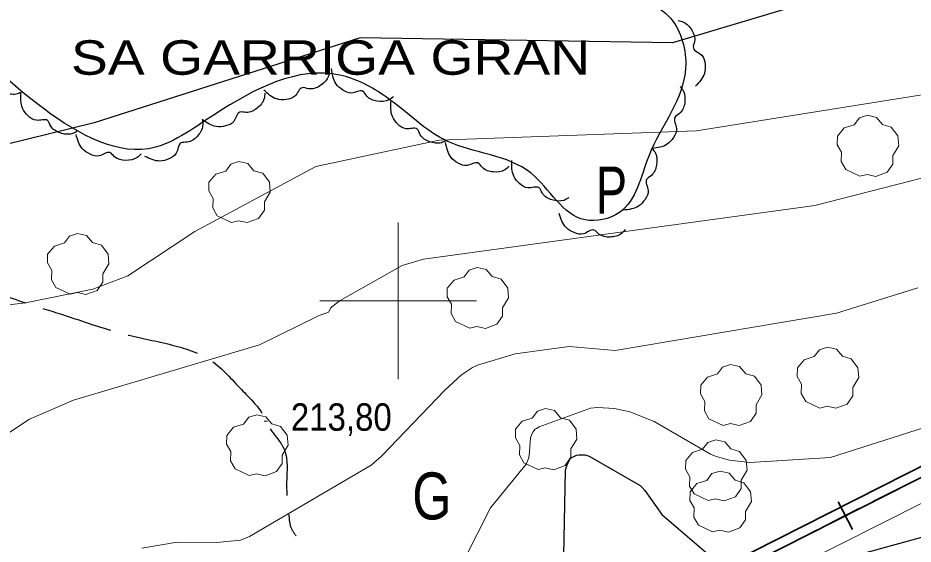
# Model space of a CAD drawing. Extents: x 480269 to 484877, y 4383588 to 4386804.
# Drawn here: x 483378.6 to 483664.3, y 4384922.4 to 4385090.3 of the extents above; entities that cross this region are included whole.
import ezdxf
from ezdxf.enums import TextEntityAlignment as Align

# ---------------------------------------------------------------- set-up
doc = ezdxf.new("R2010")
doc.units = 0
doc.header["$LTSCALE"] = 3.8
doc.linetypes.add('LONG_DASHED', pattern=[7.5, 6, -1.5])
for name, color, linetype, lineweight in [('1', 7, 'Continuous', 13), ('27', 7, 'Continuous', 25), ('29', 7, 'Continuous', 13), ('34', 7, 'Continuous', 35), ('38', 7, 'Continuous', 25), ('51', 7, 'Continuous', 13), ('7', 7, 'Continuous', 13), ('8', 7, 'Continuous', 25), ('9', 7, 'Continuous', 13)]:
    doc.layers.add(name, color=color, linetype=linetype, lineweight=lineweight)
doc.layers.add('31', color=7, linetype='Continuous')
doc.layers.add('5', color=7, linetype='Continuous')

msp = doc.modelspace()

# ---------------------------------------------------------------- linework, layer by layer
at = {"layer": '1'}
for p, q in [((483500, 4385025), (483500, 4384975)), ((483475, 4385000), (483525, 4385000))]:
    msp.add_line(p, q, dxfattribs=at)
at = {"layer": '27'}
for points in [[(483727.16, 4385128.45), (483702.11, 4385129.24), (483649.65, 4385135.5), (483626.16, 4385132.37), (483588.58, 4385137.07), (483567.44, 4385128.45), (483561.17, 4385115.92), (483569.79, 4385101.04), (483587.01, 4385090.07), (483591.71, 4385074.4), (483579.96, 4385046.2), (483570.57, 4385028.19), (483559.61, 4385025.84), (483542.38, 4385040.72), (483515.76, 4385050.9), (483496.19, 4385065), (483481.31, 4385072.05), (483441.38, 4385059.52), (483420.24, 4385048.55), (483385, 4385062.65), (483357.6, 4385086.15), (483334.89, 4385110.44), (483327.07, 4385140.2), (483309.84, 4385151.17), (483298.1, 4385151.17), (483281.65, 4385134.72), (483253.47, 4385133.15), (483239.37, 4385137.85), (483220.58, 4385130.8), (483190.05, 4385142.55), (483153.25, 4385156.65), (483117.23, 4385145.69), (483096.09, 4385136.29), (483050.68, 4385162.14), (483002.13, 4385187.2), (482983.34, 4385195.04)], [(483589.29, 4385089.45), (483591, 4385088.98), (483593.71, 4385086.33), (483594.55, 4385082.73), (483594.19, 4385080.71), (483596.86, 4385078.36), (483597.91, 4385075.56), (483597.7, 4385072.55), (483594.86, 4385068.48)], [(483379.64, 4385066.54), (483377.96, 4385065.96), (483374.22, 4385066.61), (483371.49, 4385069.1), (483370.65, 4385070.97), (483367.12, 4385071.41), (483364.67, 4385073.11), (483363.14, 4385075.72), (483363.18, 4385080.68)], [(483498.46, 4385065.15), (483497, 4385064.13), (483493.23, 4385063.71), (483489.92, 4385065.34), (483488.59, 4385066.9), (483485.08, 4385066.33), (483482.25, 4385067.28), (483480.05, 4385069.36), (483478.7, 4385074.13)], [(483477.98, 4385073.03), (483477.52, 4385071.32), (483474.9, 4385068.57), (483471.32, 4385067.69), (483469.29, 4385068.03), (483466.97, 4385065.33), (483464.19, 4385064.25), (483461.17, 4385064.42), (483457.07, 4385067.22)], [(483589.97, 4385068.38), (483591, 4385066.93), (483591.42, 4385063.16), (483589.8, 4385059.84), (483588.25, 4385058.5), (483588.82, 4385055), (483587.88, 4385052.17), (483585.81, 4385049.96), (483581.03, 4385048.6)], [(483397.42, 4385054.09), (483395.81, 4385053.34), (483392.03, 4385053.6), (483389.05, 4385055.78), (483388.01, 4385057.55), (483384.46, 4385057.61), (483381.84, 4385059.05), (483380.04, 4385061.47), (483379.56, 4385066.41)], [(483457.39, 4385066.3), (483457.16, 4385064.54), (483454.91, 4385061.48), (483451.47, 4385060.14), (483449.42, 4385060.22), (483447.46, 4385057.25), (483444.84, 4385055.82), (483441.83, 4385055.61), (483437.4, 4385057.85)], [(483515.36, 4385051.18), (483513.74, 4385050.46), (483509.96, 4385050.77), (483507.02, 4385053), (483506.01, 4385054.79), (483502.46, 4385054.91), (483499.86, 4385056.39), (483498.1, 4385058.84), (483497.7, 4385063.79)], [(483437.48, 4385057.65), (483437.54, 4385055.88), (483435.81, 4385052.5), (483432.63, 4385050.63), (483430.59, 4385050.38), (483429.13, 4385047.13), (483426.78, 4385045.3), (483423.83, 4385044.61), (483419.11, 4385046.11)], [(483417.93, 4385046.95), (483416.63, 4385045.74), (483412.95, 4385044.81), (483409.44, 4385045.96), (483407.91, 4385047.32), (483404.51, 4385046.27), (483401.58, 4385046.83), (483399.11, 4385048.58), (483397.12, 4385053.12)], [(483535.39, 4385042.92), (483534.01, 4385041.8), (483530.27, 4385041.13), (483526.86, 4385042.54), (483525.42, 4385044.01), (483521.96, 4385043.21), (483519.07, 4385043.97), (483516.74, 4385045.9), (483515.08, 4385050.57)], [(483581.07, 4385048.59), (483582.08, 4385047.13), (483582.46, 4385043.35), (483580.8, 4385040.05), (483579.23, 4385038.73), (483579.76, 4385035.22), (483578.78, 4385032.4), (483576.69, 4385030.22), (483571.9, 4385028.92)], [(483554.4, 4385032.85), (483552.81, 4385032.07), (483549.02, 4385032.23), (483546, 4385034.34), (483544.92, 4385036.09), (483541.36, 4385036.06), (483538.71, 4385037.43), (483536.85, 4385039.82), (483536.25, 4385044.74)], [(483572.45, 4385022.77), (483571.22, 4385021.49), (483567.59, 4385020.36), (483564.03, 4385021.33), (483562.42, 4385022.61), (483559.09, 4385021.38), (483556.13, 4385021.78), (483553.57, 4385023.4), (483551.34, 4385027.83)]]:
    msp.add_spline(points, degree=3, dxfattribs=at)
at = {"layer": '29'}
for points in [[(483647.36, 4385039.79), (483642.82, 4385041.91), (483641.41, 4385044.45), (483641.51, 4385047.43), (483640.14, 4385049.84), (483640.18, 4385052.59), (483642.34, 4385055.19), (483645.53, 4385056.19), (483647.18, 4385058.38), (483649.75, 4385059.21), (483652.61, 4385058.56), (483654.56, 4385056.29), (483657.37, 4385055.47), (483659.5, 4385052.62), (483659.74, 4385049.49), (483657.86, 4385046.34), (483657.86, 4385043.66), (483656.04, 4385041.05), (483652.42, 4385039.71), (483649.65, 4385040.34)], [(483446.73, 4385025.04), (483442.19, 4385027.16), (483440.78, 4385029.7), (483440.88, 4385032.68), (483439.51, 4385035.09), (483439.55, 4385037.84), (483441.71, 4385040.44), (483444.9, 4385041.44), (483446.55, 4385043.63), (483449.12, 4385044.46), (483451.98, 4385043.81), (483453.93, 4385041.54), (483456.74, 4385040.72), (483458.87, 4385037.87), (483459.11, 4385034.74), (483457.23, 4385031.59), (483457.23, 4385028.91), (483455.41, 4385026.3), (483451.79, 4385024.96), (483449.02, 4385025.59)], [(483395.22, 4385002.1), (483390.68, 4385004.22), (483389.27, 4385006.76), (483389.37, 4385009.74), (483388, 4385012.15), (483388.04, 4385014.9), (483390.2, 4385017.5), (483393.39, 4385018.5), (483395.04, 4385020.69), (483397.61, 4385021.52), (483400.47, 4385020.87), (483402.42, 4385018.6), (483405.23, 4385017.78), (483407.36, 4385014.93), (483407.6, 4385011.8), (483405.72, 4385008.65), (483405.72, 4385005.97), (483403.9, 4385003.36), (483400.28, 4385002.02), (483397.51, 4385002.65)], [(483522.81, 4384991.26), (483518.27, 4384993.38), (483516.86, 4384995.92), (483516.96, 4384998.9), (483515.59, 4385001.31), (483515.63, 4385004.06), (483517.79, 4385006.66), (483520.98, 4385007.66), (483522.63, 4385009.85), (483525.2, 4385010.68), (483528.06, 4385010.03), (483530.01, 4385007.76), (483532.82, 4385006.94), (483534.95, 4385004.09), (483535.19, 4385000.96), (483533.31, 4384997.81), (483533.31, 4384995.13), (483531.49, 4384992.52), (483527.87, 4384991.18), (483525.1, 4384991.81)], [(483634.59, 4384965.81), (483630.05, 4384967.93), (483628.64, 4384970.47), (483628.74, 4384973.45), (483627.37, 4384975.86), (483627.41, 4384978.61), (483629.57, 4384981.21), (483632.76, 4384982.21), (483634.41, 4384984.4), (483636.98, 4384985.23), (483639.84, 4384984.58), (483641.79, 4384982.31), (483644.6, 4384981.49), (483646.73, 4384978.64), (483646.97, 4384975.51), (483645.09, 4384972.36), (483645.09, 4384969.68), (483643.27, 4384967.07), (483639.65, 4384965.73), (483636.88, 4384966.36)], [(483603.71, 4384960.27), (483599.17, 4384962.39), (483597.76, 4384964.93), (483597.86, 4384967.91), (483596.49, 4384970.32), (483596.53, 4384973.07), (483598.69, 4384975.67), (483601.88, 4384976.67), (483603.53, 4384978.86), (483606.1, 4384979.69), (483608.96, 4384979.04), (483610.91, 4384976.77), (483613.72, 4384975.95), (483615.85, 4384973.1), (483616.09, 4384969.97), (483614.21, 4384966.82), (483614.21, 4384964.14), (483612.39, 4384961.53), (483608.77, 4384960.19), (483606, 4384960.82)], [(483544.6, 4384946.22), (483540.06, 4384948.34), (483538.65, 4384950.88), (483538.75, 4384953.86), (483537.38, 4384956.27), (483537.42, 4384959.02), (483539.58, 4384961.62), (483542.77, 4384962.62), (483544.42, 4384964.81), (483546.99, 4384965.64), (483549.85, 4384964.99), (483551.8, 4384962.72), (483554.61, 4384961.9), (483556.74, 4384959.05), (483556.98, 4384955.92), (483555.1, 4384952.77), (483555.1, 4384950.09), (483553.28, 4384947.48), (483549.66, 4384946.14), (483546.89, 4384946.77)], [(483452.42, 4384944.27), (483447.88, 4384946.39), (483446.47, 4384948.93), (483446.57, 4384951.91), (483445.2, 4384954.32), (483445.24, 4384957.07), (483447.4, 4384959.67), (483450.59, 4384960.67), (483452.24, 4384962.86), (483454.81, 4384963.69), (483457.67, 4384963.04), (483459.62, 4384960.77), (483462.43, 4384959.95), (483464.56, 4384957.1), (483464.8, 4384953.97), (483462.92, 4384950.82), (483462.92, 4384948.14), (483461.1, 4384945.53), (483457.48, 4384944.19), (483454.71, 4384944.82)], [(483598.94, 4384936.26), (483594.4, 4384938.38), (483592.99, 4384940.92), (483593.09, 4384943.9), (483591.72, 4384946.31), (483591.76, 4384949.06), (483593.92, 4384951.66), (483597.11, 4384952.66), (483598.76, 4384954.85), (483601.33, 4384955.68), (483604.19, 4384955.03), (483606.14, 4384952.76), (483608.95, 4384951.94), (483611.08, 4384949.09), (483611.32, 4384945.96), (483609.44, 4384942.81), (483609.44, 4384940.13), (483607.62, 4384937.52), (483604, 4384936.18), (483601.23, 4384936.81)], [(483600.32, 4384926.29), (483595.78, 4384928.41), (483594.37, 4384930.95), (483594.47, 4384933.93), (483593.1, 4384936.34), (483593.14, 4384939.09), (483595.3, 4384941.69), (483598.49, 4384942.69), (483600.14, 4384944.88), (483602.71, 4384945.71), (483605.57, 4384945.06), (483607.52, 4384942.79), (483610.33, 4384941.97), (483612.46, 4384939.12), (483612.7, 4384935.99), (483610.82, 4384932.84), (483610.82, 4384930.16), (483609, 4384927.55), (483605.38, 4384926.21), (483602.61, 4384926.84)]]:
    msp.add_lwpolyline(points, close=True, dxfattribs=at)
at = {"layer": '34'}
for p, q in [((483660.53, 4384940.49), (483651.61, 4384935.97)), ((483644.95, 4384927), (483640.43, 4384935.92)), ((483647.15, 4384933.72), (483638.23, 4384929.2)), ((483633.77, 4384926.94), (483624.85, 4384922.42))]:
    msp.add_line(p, q, dxfattribs=at)
for points in [[(484100.12, 4385166.55), (483464.12, 4384844.55), (483456.6, 4384851.12)], [(484100.12, 4385166.55), (483464.12, 4384844.55), (483456.6, 4384851.12)], [(484102, 4385164), (483466, 4384842), (483458.48, 4384848.57)]]:
    msp.add_lwpolyline(points, dxfattribs=at)
at = {"layer": '38', "linetype": 'LONG_DASHED'}
for points in [[(483233.78, 4385308.48), (483231.33, 4385296.55), (483230.91, 4385293.11), (483235.93, 4385285.42), (483240.31, 4385278.42), (483246.13, 4385265.75), (483249.19, 4385254.19), (483250.95, 4385239.65), (483251.67, 4385235.57), (483259.07, 4385218.52), (483264.9, 4385207.07), (483274.17, 4385195.71), (483279.16, 4385187.48), (483284.25, 4385179.98), (483291.63, 4385170.78), (483301.3, 4385157.59), (483309.29, 4385151.15), (483321.54, 4385145.01), (483327, 4385142.18), (483343.13, 4385134.24), (483347, 4385132.08), (483362.74, 4385127.22), (483375.61, 4385123.19), (483382.29, 4385121.24), (483392.05, 4385122.1), (483398.94, 4385123.93), (483414.83, 4385125.71), (483429.38, 4385125.27), (483445.33, 4385122.89), (483453.47, 4385121.77), (483466.47, 4385118.65), (483477.91, 4385115.57), (483493.05, 4385113.4), (483510.22, 4385112.03), (483519.85, 4385111.14), (483530.18, 4385111.14), (483538.19, 4385111.65), (483548.34, 4385113.76), (483562.15, 4385118.29), (483574.67, 4385120.81), (483584.06, 4385120.84), (483597.73, 4385121.64), (483609.56, 4385123.49), (483619.04, 4385124.67), (483631.84, 4385126.21), (483639.65, 4385127.78), (483655.03, 4385131.45), (483674.84, 4385131.69), (483682.68, 4385129.51), (483694.76, 4385128.42), (483706.71, 4385129.77), (483727.91, 4385131.14), (483743.49, 4385131.99), (483748.81, 4385132.22), (483749.33, 4385132.23), (483754.02, 4385132.33), (483765.96, 4385128.73), (483777.67, 4385122.7), (483794.73, 4385115.2), (483809.09, 4385106.78), (483819.65, 4385098.99), (483831.87, 4385091.54), (483838.23, 4385088.12), (483855.98, 4385080.29), (483870.77, 4385074.61), (483884.05, 4385070.06), (483896.47, 4385067.15), (483906.8, 4385065.32), (483909.71, 4385065)], [(483191.41, 4385172.62), (483199.18, 4385164.92), (483210.2, 4385152.64), (483216.4, 4385142.97), (483224.72, 4385131.98), (483237.45, 4385125.24), (483244.64, 4385121.93), (483253.17, 4385116.33), (483258.55, 4385108.88), (483261.18, 4385098.85), (483261.29, 4385084.08), (483260.9, 4385080.56), (483262.31, 4385067.93), (483266.69, 4385057.75), (483272.69, 4385049.99), (483280.76, 4385041.19), (483290.56, 4385033.86), (483298.87, 4385028.57), (483312.94, 4385022.92), (483330.8, 4385021.02), (483345.47, 4385013.87), (483353.53, 4385009.78), (483365.16, 4385005.06), (483380.96, 4384999.4), (483392.8, 4384995.63), (483412.21, 4384989.49), (483426.88, 4384986.14), (483440.33, 4384980.88), (483449.91, 4384971.7), (483456.88, 4384963.51), (483459.13, 4384959.17), (483462.74, 4384954.22), (483463.87, 4384951.74), (483464.35, 4384942.25), (483465.12, 4384930.74), (483465.7, 4384927.75), (483467.32, 4384925.06)]]:
    msp.add_spline(points, degree=3, dxfattribs=at)
at = {"layer": '51'}
msp.add_lwpolyline([(483946.77, 4385079.46), (483923.46, 4385067.75), (483887.47, 4385048.7), (483848.49, 4385029.46), (483751.89, 4384977.68), (483681.97, 4384942.9), (483613.29, 4384908.35), (483585.87, 4384894.64), (483579.92, 4384890.82), (483576.83, 4384888.22), (483553.97, 4384877.65), (483489.05, 4384843.35), (483479.15, 4384838.43)], dxfattribs=at)
at = {"layer": '7'}
msp.add_line((483457.19, 4384961.58), (483458.19, 4384961.58), dxfattribs=at)
at = {"layer": '8'}
for points in [[(483537.09, 4385272.64), (483603.72, 4385224.87), (483699.79, 4385143.59), (483704.39, 4385137.87), (483705.92, 4385134.65), (483706.44, 4385133.01), (483706.57, 4385132.14), (483706.59, 4385131.1), (483706.53, 4385130.45), (483706.19, 4385129.12), (483704.7, 4385125.62), (483701.65, 4385120.64), (483700.27, 4385119.15), (483689.93, 4385112.94), (483587.49, 4385082.35), (483487.82, 4385083.94), (483402.86, 4385056.78), (483324.11, 4385037.48)], [(483552.29, 4384891.54), (483553.42, 4384945.89), (483553.53, 4384946.46), (483553.98, 4384947.99), (483554.97, 4384949.79), (483556.69, 4384950.67), (483557.04, 4384950.79), (483557.59, 4384950.9), (483559.68, 4384950.84), (483560.91, 4384950.42), (483577.26, 4384941.06), (483577.89, 4384940.48), (483578.75, 4384939.53), (483584.14, 4384931.88), (483598.32, 4384919.71)], [(483643.91, 4384918.19), (483684.91, 4384929.51)]]:
    msp.add_lwpolyline(points, dxfattribs=at)
at = {"layer": '9'}
for points in [[(483798.3, 4385072.74), (483633.02, 4385030.39), (483507.99, 4385013.28), (483501.18, 4385011.34), (483481.4, 4385000.16), (483478.81, 4384998.13), (483478.47, 4384997.79), (483477.76, 4384996.36), (483474.47, 4384995.18), (483455.65, 4384985.99), (483396.36, 4384968.35), (483382.26, 4384962.21), (483369.59, 4384954.01)], [(483346.38, 4384995.22), (483380.94, 4384999.42), (483402.51, 4385003.74), (483413.61, 4385007.96), (483435.01, 4385022.13), (483473.71, 4385042.92), (483513.07, 4385051.28), (483595.21, 4385054.24), (483689.15, 4385069.3)], [(483418.17, 4384921.05), (483429.45, 4384922.99), (483442.11, 4384922.87), (483449.57, 4384923.62), (483452.47, 4384924.8), (483491.31, 4384947.6), (483494.62, 4384950.45), (483514.89, 4384971.46), (483520.14, 4384976.41), (483523.64, 4384978.7), (483525.28, 4384979.44), (483537.28, 4384983.12), (483554.58, 4384985.46), (483569.25, 4384984.17), (483639.89, 4384996.04), (483665.85, 4385004.11)], [(483512.6, 4384900.73), (483529.43, 4384933.92), (483540.84, 4384947.9), (483541.17, 4384948.59), (483541.58, 4384949.67), (483541.76, 4384950.66), (483542.22, 4384956.25), (483542.58, 4384957.44), (483543, 4384958.24), (483543.24, 4384958.58), (483543.65, 4384959.02), (483544.1, 4384959.33), (483544.93, 4384959.81), (483561.32, 4384965.72), (483563.64, 4384965.97), (483568.99, 4384965.67), (483573.88, 4384964.61), (483581.71, 4384961.53), (483599.62, 4384951.08), (483601.45, 4384950.35), (483605.72, 4384949.15), (483612.17, 4384948.48), (483638.01, 4384949.98), (483767.33, 4384991.29)]]:
    msp.add_lwpolyline(points, dxfattribs=at)

# ---------------------------------------------------------------- texts
at = {"layer": '31'}
for s, width, p in [('P', 0.75, (483568.03, 4385027.86)), ('G', 0.8, (483510.71, 4384930.25))]:
    msp.add_text(s, height=15, dxfattribs=dict(at, width=width)).set_placement(p, align=Align.CENTER)
at = {"layer": '5', "width": 1.2}
msp.add_text('SA GARRIGA GRAN', height=11, dxfattribs=at).set_placement((483395.49, 4385072.15))
at = {"layer": '7', "width": 0.9}
msp.add_text('213,80', height=8.75, dxfattribs=at).set_placement((483465.7, 4384958.56))

doc.saveas('drawing.dxf')
